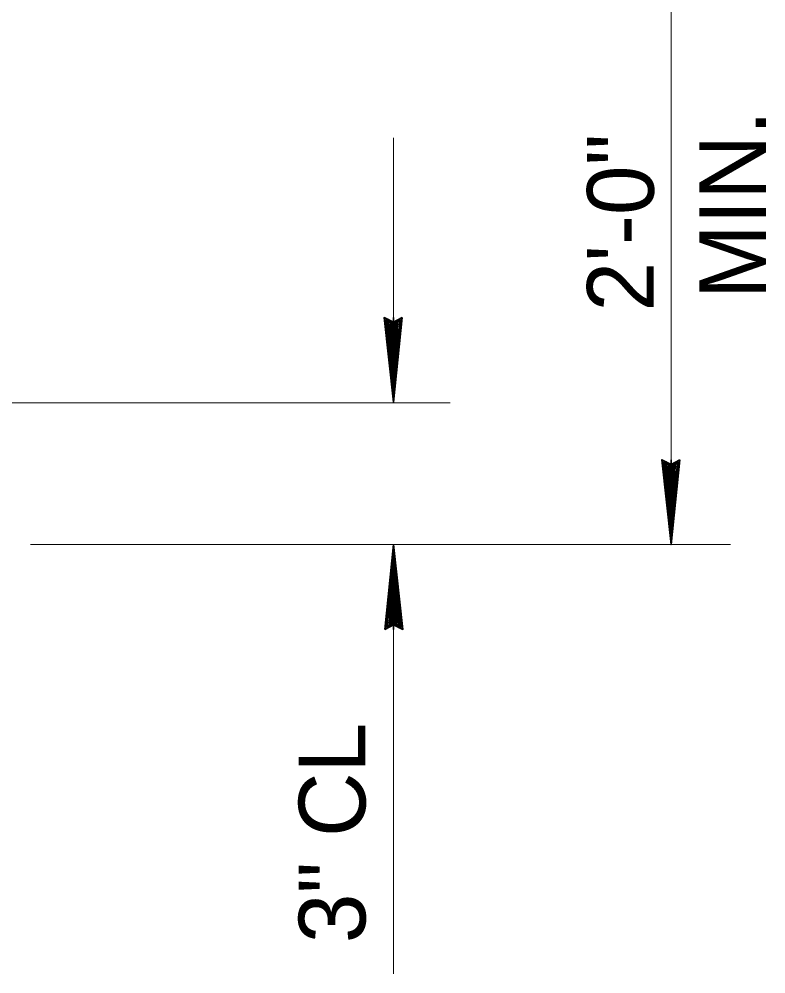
# Model space of a CAD drawing. Extents: x 14.14 to 17.34, y -1.61 to 0.38.
# Drawn here: x 16.0995 to 16.1928, y -0.5509 to -0.4318 of the extents above; entities that cross this region are included whole.
import ezdxf

# ---------------------------------------------------------------- set-up
doc = ezdxf.new("R2010")
doc.units = 0
doc.header["$LTSCALE"] = 0.0033
doc.layers.add('1', color=7, linetype='Continuous', lineweight=40)

msp = doc.modelspace()

# ---------------------------------------------------------------- linework, layer by layer
at = {"layer": '1', "lineweight": 13}
for p, q in [((16.180917, -0.414667), (16.180917, -0.497333)), ((16.14625, -0.4795), (16.14625, -0.446583)), ((16.082667, -0.479667), (16.153333, -0.479667)), ((16.100917, -0.497333), (16.188333, -0.497333)), ((16.14625, -0.550917), (16.14625, -0.50725))]:
    msp.add_line(p, q, dxfattribs=at)
at = {"layer": '1', "lineweight": 35}
for p, q in [((16.145167, -0.46925), (16.146, -0.476583)), ((16.145333, -0.46925), (16.146083, -0.476583)), ((16.145417, -0.46925), (16.14625, -0.476583)), ((16.145583, -0.469167), (16.146333, -0.4765)), ((16.147083, -0.46925), (16.146083, -0.477083)), ((16.14625, -0.469), (16.14625, -0.479583)), ((16.147083, -0.46925), (16.14625, -0.477083)), ((16.14725, -0.46925), (16.146333, -0.477083)), ((16.14725, -0.46925), (16.146333, -0.477083)), ((16.147167, -0.46925), (16.146333, -0.477083)), ((16.179833, -0.487), (16.180667, -0.494333)), ((16.18, -0.487), (16.18075, -0.494333)), ((16.180083, -0.487), (16.180917, -0.494333)), ((16.18025, -0.486917), (16.181, -0.49425)), ((16.18175, -0.487), (16.18075, -0.494833)), ((16.180917, -0.48675), (16.180917, -0.497333)), ((16.18175, -0.487), (16.180917, -0.494833)), ((16.181917, -0.487), (16.181, -0.494833)), ((16.181917, -0.487), (16.181, -0.494833)), ((16.181833, -0.487), (16.181, -0.494833)), ((16.14625, -0.507917), (16.14625, -0.497333)), ((16.14525, -0.507667), (16.146167, -0.499833)), ((16.14525, -0.507667), (16.146167, -0.499833)), ((16.145333, -0.507667), (16.146167, -0.499833)), ((16.145417, -0.507667), (16.14625, -0.499833)), ((16.145417, -0.507667), (16.146417, -0.499833)), ((16.146917, -0.50775), (16.146167, -0.500417)), ((16.147083, -0.507667), (16.14625, -0.500333)), ((16.147167, -0.507667), (16.146417, -0.500333)), ((16.147333, -0.507667), (16.1465, -0.500333))]:
    msp.add_line(p, q, dxfattribs=at)
for points in [[(16.147333, -0.469), (16.14625, -0.479583), (16.145083, -0.469), (16.14625, -0.469583)], [(16.146333, -0.46975), (16.146417, -0.474417), (16.146333, -0.474417), (16.146333, -0.4735), (16.146417, -0.46975), (16.1465, -0.47275), (16.146583, -0.469583), (16.146667, -0.471833), (16.14675, -0.469583), (16.1465, -0.473083), (16.146333, -0.47775), (16.146083, -0.476833), (16.146083, -0.478083), (16.146083, -0.46975), (16.145917, -0.472167), (16.145917, -0.469583), (16.146333, -0.474917), (16.145667, -0.469583)], [(16.182, -0.48675), (16.180917, -0.497333), (16.17975, -0.48675), (16.180917, -0.487333)], [(16.181, -0.4875), (16.181083, -0.492167), (16.181, -0.492167), (16.181, -0.49125), (16.181083, -0.4875), (16.181167, -0.4905), (16.18125, -0.487333), (16.181333, -0.489583), (16.181417, -0.487333), (16.181167, -0.490833), (16.181, -0.4955), (16.18075, -0.494583), (16.18075, -0.495833), (16.18075, -0.4875), (16.180583, -0.489917), (16.180583, -0.487333), (16.181, -0.492667), (16.180333, -0.487333)], [(16.145167, -0.507917), (16.14625, -0.497333), (16.147417, -0.507917), (16.14625, -0.507333)], [(16.146167, -0.507167), (16.146083, -0.5025), (16.146167, -0.5025), (16.146167, -0.503417), (16.146083, -0.507167), (16.146, -0.504167), (16.145917, -0.507333), (16.145833, -0.505083), (16.14575, -0.507333), (16.146, -0.503833), (16.146167, -0.499167), (16.146417, -0.500083), (16.146417, -0.498833), (16.146417, -0.507167), (16.146583, -0.50475), (16.146583, -0.507333), (16.146167, -0.502), (16.146833, -0.507333)]]:
    msp.add_lwpolyline(points, close=True, dxfattribs=at)
for points in [[(16.146333, -0.46975), (16.147083, -0.469333), (16.146833, -0.469583), (16.1465, -0.46975), (16.146583, -0.47), (16.146917, -0.469833), (16.146167, -0.469667), (16.145667, -0.4695), (16.14525, -0.46925)], [(16.181, -0.4875), (16.18175, -0.487083), (16.1815, -0.487333), (16.181167, -0.4875), (16.18125, -0.48775), (16.181583, -0.487583), (16.180833, -0.487417), (16.180333, -0.48725), (16.179917, -0.487)], [(16.146167, -0.507167), (16.145417, -0.507583), (16.145667, -0.507333), (16.146, -0.507167), (16.145917, -0.506917), (16.145583, -0.507083), (16.146333, -0.50725), (16.146833, -0.507417), (16.14725, -0.507667)]]:
    msp.add_lwpolyline(points, dxfattribs=at)

# ---------------------------------------------------------------- texts
at = {"layer": '1'}
for s, height, p in [('MIN.', 0.008334, (16.19275, -0.466667)), ('2\'-0"', 0.008333, (16.17875, -0.46825)), ('3" CL', 0.008334, (16.14275, -0.547083))]:
    msp.add_text(s, height=height, rotation=90, dxfattribs=at).set_placement(p)

doc.saveas('drawing.dxf')
